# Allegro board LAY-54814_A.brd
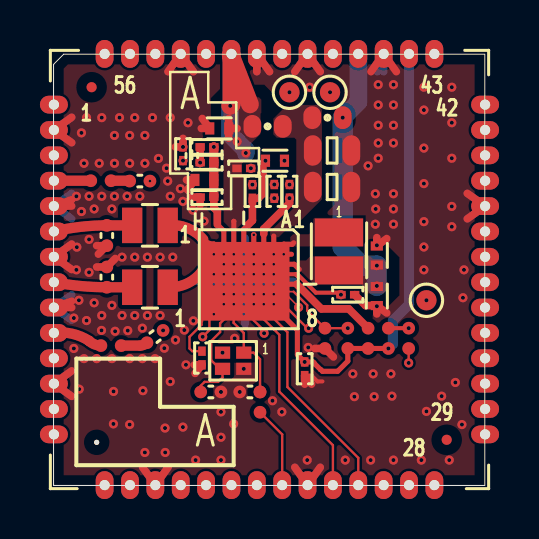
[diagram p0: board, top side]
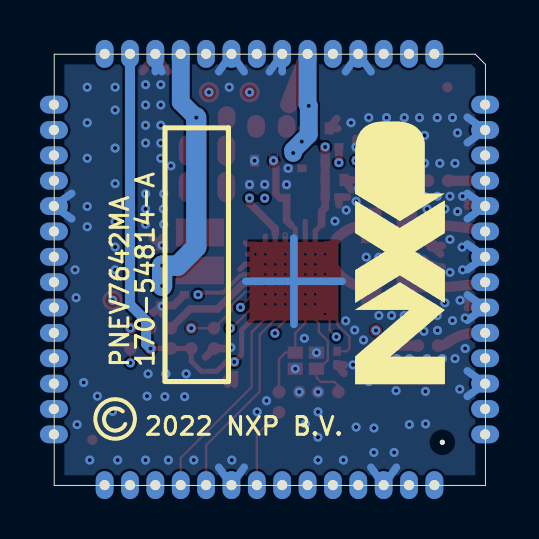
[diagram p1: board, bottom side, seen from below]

Outline 21.59 x 21.59 mm; copper layers: TOP, L2_GND_1, L3_INT_1, L4_INT_2, L5_GND_2, BOTTOM. Coordinates in mm from the lower left corner of the outline.
Outline path: 0,21.08 0,0 21.59,0 21.59,21.59 0.51,21.59 0,21.08

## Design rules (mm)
constraint set DEFAULT: min track width 0.117
net group USB: nets ATX_C ATX_D
net group PWR: nets VBAT VDDIO VDDPA

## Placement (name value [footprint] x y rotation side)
C1  18PF  [CC0402_25]  9.83 4.68 180 top
C2  18PF  [CC0402_25]  7.87 4.68 0 top
C5  0.1uF  [CC0201]  7.43 6.38 270 top
C7  1000pF  [CC0402_25]  5.08 7.45 217.3 top
C8  0.1uF  [CC0201]  12.57 5.84 270 top
C9  0.22uF  [CC0201]  14.73 9.55 0 top
C10  4.7uF  [CC0402_TOL0P15]  16.19 9.48 270 top
C11  0.22uF  [CC0201]  11.81 14.73 90 top
C12  560pF  [CC0402_25]  2.67 10.43 90 top
C13  4.7uF  [CC0402_TOL0P15]  16.19 11.51 90 top
C14  560pF  [CC0402_25]  2.67 12.51 270 top
C15  100pF  [CC0201]  7.68 14.43 180 top
C16  0.1uF  [CC0201]  11.05 14.72 90 top
C17  1uf  [CC0201]  9.96 14.72 90 top
C19  22uF  [CC0805_OV]  13.94 14.94 0 top
C20  4.7uF  [CC0402_TOL0P15]  7.55 15.3 180 top
C21  1000pF  [CC0402_25]  4.32 15.24 180 top
C22  100pF  [CC0201]  9.52 15.88 0 top
C23  100pF  [CC0201]  7.68 16.16 0 top
C24  4.7uF  [CC0402_TOL0P15]  11.09 16.26 0 top
C26  0.22uF  [CC0201]  6.48 16.61 90 top
C27  22uF  [CC0805_OV]  13.94 16.77 0 top
C28  0.22uF  [CC0201]  7.68 16.95 0 top
C29  4.7uF  [CC0402_TOL0P15]  8.29 17.88 180 top
L1  160nH  [IND0805HQ]  4.83 9.92 180 top
L2  1.0uH  [IND_1008_SMD]  14.29 11.72 270 top
L3  160nH  [IND0805HQ]  4.83 13.02 180 top
NOREF  -  []  10.18 0.02 0 top
NOREF#2  -  [unnamed#2]  2.16 2.16 270 top
NOREF#3  -  []  -27.72 -40.64 0 top
NOREF#4  -  []  8.14 6.89 0 top
NOREF#5  -  []  14.71 9.41 90 top
NOREF#6  -  []  7.07 15.3 0 top
NOREF#7  -  []  -53.92 -161.42 0 top
NOREF#8  -  [unnamed#2]  1.9 19.94 180 top
NOREF#9  -  []  7.47 8.02 0 top
NOREF#10  -  []  6.97 14.97 90 top
NOREF#11  -  []  14.71 10.06 0 top
NOREF#12  -  []  21.61 5.1 90 top
NOREF#13  -  []  -267.27 261.62 0 top
NOREF#14  -  []  7.37 12.19 0 top
NOREF#15  -  []  7.82 17.88 0 top
NOREF#16  -  []  7.72 18.2 0 top
NOREF#17  -  []  15.36 10.29 90 top
NOREF#18  -  []  9.84 5.59 90 top
NOREF#19  -  []  2.16 2.16 0 top
NOREF#20  -  []  16.19 9.01 90 top
NOREF#21  -  []  10.61 16.26 0 top
NOREF#22  -  []  7.37 8.25 90 top
NOREF#23  -  []  9.52 5.84 90 top
NOREF#24  -  []  7.72 17.55 90 top
NOREF#25  -  []  0.02 0.02 0 top
NOREF#26  -  []  21.61 2.56 90 top
NOREF#27  -  []  15.36 10.94 0 top
NOREF#28  -  []  8.46 6.65 0 top
NOREF#29  -  []  16.19 11.04 90 top
NOREF#30  -  [unnamed#2]  19.68 2.29 180 top
NOREF#31  -  []  -294.83 -257.94 0 top
NOREF#32  -  []  21.61 0.02 90 top
NOREF#33  -  []  7.47 8.02 90 top
NOREF#34  -  []  11.66 15.93 90 top
NOREF#35  -  []  6.97 15.62 0 top
NOREF#36  -  []  10.51 15.93 0 top
NOREF#37  -  []  18.54 3.3 180 bottom
NOREF#38  -  []  2.03 5.08 90 bottom
NOREF#39  -  []  16.55 17.39 270 bottom
P1  PN76xx-M  [MODULE56_1P52_25X25MM]  10.81 10.81 0 top
R1  0  [RC0402_25]  10.34 4.17 90 top
R2  0  [RC0402_25]  2.88 7 180 top
R3  0  [RC0402_25]  2.37 15.26 180 top
R4  0  [RC0603_OV]  10.72 17.98 180 top
R5  0  [RC0402_25]  15.75 7.37 270 top
R6  0  [RC0402_25]  13.59 7.37 90 top
R7  0  [RC0402_25]  14.73 7.37 90 top
R8  0  [RC0603_OV]  13.72 18.41 180 top
R9  10.0K  [RC0402_25]  16.76 7.37 90 top
R10  0  [RC0402_25]  17.78 7.37 270 top
TP1  -  [TPAD_040]  13.84 19.68 180 top
TP2  -  [TPAD_040]  11.81 19.68 180 top
TP3  -  [TPAD_040]  18.67 9.27 180 top
U1  PN7642EV/C100  [VFBGA64_0P5_4P6X4P6]  9.77 10.32 270 top
Y1  27.12MHz  [XTAL4_1P6X1P2]  8.99 6.24 180 top

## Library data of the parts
C1 C2 C7 C10 C12-C14 C19-C21 C24 C27 C29 = CAP_NP
C5 C8 C16 = CAP_NP: Tolerance: TOLERANCE; User Part Number: 150-80059
C9 C11 C26 C28 = CAP_NP: Tolerance: TOLERANCE; User Part Number: 150-79474
C15 C22 C23 = CAP_NP: Tolerance: TOLERANCE; User Part Number: 150-75742
C17 = CAP_NP: Tolerance: TOLERANCE; User Part Number: 150-79855
L1 L3 = INDUCTOR: tolerance: 5%
L2 = INDUCTOR: tolerance: 20%
P1 = TP_RECT_56P_EP
R1-R8 R10 = RES
R9 = RES: tolerance: 5%
TP1-TP3 = TESTLOOP
U1 = PN7642EV_VBGA64
Y1 = XTAL_13

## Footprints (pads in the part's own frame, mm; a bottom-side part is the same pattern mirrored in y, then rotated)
CC0201
  rect 0.47x0.381 smd: 1(-0.343,0) 2(0.343,0)
CC0402_25
  round 0.635 smd: 1(-0.508,0) 2(0.508,0)
CC0402_TOL0P15
  rect 0.457x0.61 smd: 1(-0.475,0) 2(0.475,0)
CC0805_OV
  oval 0.889x1.524 smd: 1(-0.965,0) 2(0.965,0)
IND0805HQ
  rect 1.016x1.778 smd: 1(-0.889,0) 2(0.889,0)
IND_1008_SMD
  rect 1.397x2.413 smd: 1(-0.95,0) 2(0.95,0)
MODULE56_1P52_25X25MM
  oval 1.397x0.889 hole 0.508: 1(-10.795,8.255) 2(-10.795,6.985) 3(-10.795,5.715) 4(-10.795,4.445) 5(-10.795,3.175) 6(-10.795,1.905) 7(-10.795,0.635) 8(-10.795,-0.635) 9(-10.795,-1.905) 10(-10.795,-3.175) 11(-10.795,-4.445) 12(-10.795,-5.715) 13(-10.795,-6.985) 14(-10.795,-8.255) 29(10.795,-8.255) 30(10.795,-6.985) 31(10.795,-5.715) 32(10.795,-4.445) 33(10.795,-3.175) 34(10.795,-1.905) 35(10.795,-0.635) 36(10.795,0.635) 37(10.795,1.905) 38(10.795,3.175) 39(10.795,4.445) 40(10.795,5.715) 41(10.795,6.985) 42(10.795,8.255)
  oval 0.889x1.397 hole 0.508: 15(-8.255,-10.795) 16(-6.985,-10.795) 17(-5.715,-10.795) 18(-4.445,-10.795) 19(-3.175,-10.795) 20(-1.905,-10.795) 21(-0.635,-10.795) 22(0.635,-10.795) 23(1.905,-10.795) 24(3.175,-10.795) 25(4.445,-10.795) 26(5.715,-10.795) 27(6.985,-10.795) 28(8.255,-10.795) 43(8.255,10.795) 44(6.985,10.795) 45(5.715,10.795) 46(4.445,10.795) 47(3.175,10.795) 48(1.905,10.795) 49(0.635,10.795) 50(-0.635,10.795) 51(-1.905,10.795) 52(-3.175,10.795) 53(-4.445,10.795) 54(-5.715,10.795) 55(-6.985,10.795) 56(-8.255,10.795)
  rect 4.445x3.937 smd: 57(-1.224,-0.589)
RC0402_25
  round 0.635 smd: 1(-0.508,0) 2(0.508,0)
RC0603_OV
  oval 0.889x1.143 smd: 1(-0.762,0) 2(0.762,0)
TPAD_040
  round 1.016 smd: 1(0,0)
unnamed#2
  round 0.254 hole 0.635 unplated: (0,0)
VFBGA64_0P5_4P6X4P6
  round 0.279 smd: A1(-1.75,1.75) A2(-1.25,1.75) A3(-0.75,1.75) A4(-0.25,1.75) A5(0.25,1.75) A6(0.75,1.75) A7(1.25,1.75) A8(1.75,1.75) B1(-1.75,1.25) B2(-1.25,1.25) B3(-0.75,1.25) B4(-0.25,1.25) B5(0.25,1.25) B6(0.75,1.25) B7(1.25,1.25) B8(1.75,1.25) C1(-1.75,0.75) C2(-1.25,0.75) C3(-0.75,0.75) C4(-0.25,0.75) C5(0.25,0.75) C6(0.75,0.75) C7(1.25,0.75) C8(1.75,0.75) D1(-1.75,0.25) D2(-1.25,0.25) D3(-0.75,0.25) D4(-0.25,0.25) D5(0.25,0.25) D6(0.75,0.25) D7(1.25,0.25) D8(1.75,0.25) E1(-1.75,-0.25) E2(-1.25,-0.25) E3(-0.75,-0.25) E4(-0.25,-0.25) E5(0.25,-0.25) E6(0.75,-0.25) E7(1.25,-0.25) E8(1.75,-0.25) F1(-1.75,-0.75) F2(-1.25,-0.75) F3(-0.75,-0.75) F4(-0.25,-0.75) F5(0.25,-0.75) F6(0.75,-0.75) F7(1.25,-0.75) F8(1.75,-0.75) G1(-1.75,-1.25) G2(-1.25,-1.25) G3(-0.75,-1.25) G4(-0.25,-1.25) G5(0.25,-1.25) G6(0.75,-1.25) G7(1.25,-1.25) G8(1.75,-1.25) H1(-1.75,-1.75) H2(-1.25,-1.75) H3(-0.75,-1.75) H4(-0.25,-1.75) H5(0.25,-1.75) H6(0.75,-1.75) H7(1.25,-1.75) H8(1.75,-1.75)
XTAL4_1P6X1P2
  rect 0.762x0.61 smd: 1(-0.531,-0.405) 2(0.531,-0.405) 3(0.531,0.405) 4(-0.531,0.405)

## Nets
GND: C1.2 C2.2 C5.2 C8.2 C9.2 C10.2 C11.2 C12.2 C13.2 C14.2 C15.2 C16.2 C17.2 C19.2 C20.2 C22.2 C24.2 C26.2 C27.2 C29.2 P1.2 P1.5 P1.7 P1.9 P1.12 P1.17 P1.23 P1.38 P1.45 P1.48 P1.50 P1.53 P1.57(EPAD) R6.1 U1.A2 U1.B2 U1.C3 U1.D3 U1.E3 U1.F3 U1.F4 U1.G3 U1.H2 Y1.2 Y1.4
PVDDOUT: R5.1 U1.A5
VBAT: C17.1 C24.1 P1.49 U1.E1
VBATPWR: C10.1 C13.1 L2.2 P1.46 R8.1 U1.A3
VDDBOOST: C19.1 C27.1 R4.1 R8.2 U1.B1
VDDC: C11.1 TP1.1(PIN1) U1.C1
VDDIO: C8.1 P1.44 R5.2 R7.1 R9.1 U1.A8
VDDNV: C9.1 TP3.1(PIN1) U1.A4
VDDPA: C15.1 C20.1 C23.2 C28.2 P1.52 U1.G1
AD1: P1.1 U1.E2
ATX_A: P1.34 U1.E6
ATX_B: P1.35 U1.E5
ATX_C: P1.36 U1.D6
ATX_D: P1.37 U1.D5
AUX1: P1.18 U1.G7
AUX2: P1.19 U1.F7
BOOST_LX: L2.1 U1.A1
C_RXN: C21.2 R3.1
C_RXP: C7.2 R2.1
CLK_IN: P1.22 R1.1
CT_CLK: P1.56 U1.E4
CT_INT: P1.54 U1.C4
CT_IO: P1.55 U1.D4
DWL_REQ: P1.27 U1.A7
GPIO0: P1.28 U1.E8
GPIO1: P1.31 U1.D8
GPIO2: P1.29 U1.E7
GPIO3: P1.30 U1.D7
GPIO4: P1.32 U1.C5
GPIO5: P1.33 U1.B5
HOSTIF_SEL0: P1.20 U1.C7
HOSTIF_SEL1: P1.21 U1.C6
I2CM_SCL: P1.40 U1.B6
I2CM_SDA: P1.39 U1.A6
IRQ: P1.26 U1.B7
MOD_RXN: P1.4 R3.2
MOD_RXP: P1.10 R2.2
MOD_TX1: C14.1 L3.2 P1.6
MOD_TX2: C12.1 L1.2 P1.8
MOD_VEN: P1.43 R10.2
PRD1: P1.41 U1.B4
PRD2: P1.42 U1.G4
RXN: C21.1 U1.H4
RXP: C7.1 U1.H5
SPIM_MISO: P1.16 U1.F6
SPIM_MOSI: P1.13 U1.F5
SPIM_NSS: P1.15 U1.G6
SPIM_SCLK: P1.14 U1.G5
SWDCLK: P1.24 U1.C8
SWDIO: P1.25 U1.B8
TCVCM: C26.1 U1.G2
TEST: R6.2 R7.2 U1.C2
TX1: L3.1 U1.H1
TX2: L1.1 U1.H3
TXVCASC: C23.1 C28.1 U1.F2
USB_VBUS: P1.47 U1.D1
VEN: R9.2 R10.1 U1.B3
VMID: C5.1 U1.H6
VREF: C16.1 TP2.1(PIN1) U1.D2
VTUNE1: P1.11 U1.H7
VTUNE2: P1.3 U1.H8
VUP: C22.1 C29.1 P1.51 R4.2 U1.F1
XTAL1: C1.1 R1.2 U1.F8 Y1.1
XTAL2: C2.1 U1.G8(XTAL2) Y1.3

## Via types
v1: diameter 0.457, hole 0.203, TOP to BOTTOM, 141 vias
v2: diameter 0.279, hole 0.13, TOP to L2_GND_1, 43 vias
v3: diameter 0.254, hole 0.13, L2_GND_1 to L3_INT_1, 34 vias
v4: diameter 0.279, hole 0.13, L3_INT_1 to L4_INT_2, 17 vias
v5: diameter 0.457, hole 0.206, TOP to BOTTOM, 31 vias

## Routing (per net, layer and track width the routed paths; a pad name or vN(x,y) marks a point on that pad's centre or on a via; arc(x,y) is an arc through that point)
GND: length 152.7
  TOP w0.203: C8.2 12.92,5.5 13.21,5.21 13.46,5.21
  TOP w0.254: 11.91,11.57 v2(11.52,11.57) v2(11.02,11.57)
  TOP w0.279: v2(8.02,11.57) 7.51,11.57
  TOP w0.381: 15.89,20.72 P1.45 17.16,20.72 ; 20.72,13.35 P1.38 20.72,14.62 ; 13.35,20.72 P1.48 12.08,20.72 ; 0.91,4.46 P1.12 0.91,5.73 ; 7.09,5.61 C5.2 7.05,6.04 ; 2.16,10.94 C12.2 3.09,11.36 ; 5.73,20.72 P1.53 7,20.72 ; 0.91,17.16 P1.2 0.91,18.43 ; 5.73,0.91 P1.17 4.46,0.91 ; 6.66,15.3 C20.2 6.7,14.8 ; 16.19,12.41 C13.2 16.68,12.36 ; 7.4,17.88 C29.2 7.45,18.37 ; 2.16,12.01 C14.2 2.24,11.58 ; 0.91,8.91 P1.9 0.91,9.22 ; 14.01,6.43 R6.1 13.08,6.86 ; 0.91,10.81 P1.7 0.91,12.08 ; C10.2 15.62,9.01 C9.2 ; C10.2 16.68,8.63 ; C10.2 16.19,8.59 ; 12.08,0.91 P1.23 13.35,0.91 ; 0.91,14.3 P1.5 0.91,13.99 ; 6.91,14.43 C15.2 7.34,14.05 ; 12.92,5.07 C8.2 12.57,5.07 ; 6.1,16.95 v5(6.48,16.95) 6.48,17.38 ; 10.81,20.72 P1.50 10.18,20.72
  L2_GND_1 w0.381: 0.91,14.62 P1.5 0.91,13.35 ; 10.81,20.72 P1.50 9.54,20.72 ; 20.72,14.62 P1.38 20.72,13.35 ; 7,20.72 P1.53 5.73,20.72 ; 15.89,20.72 P1.45 17.16,20.72 ; 0.91,5.73 P1.12 0.91,4.46 ; 4.46,0.91 P1.17 5.73,0.91 ; 12.08,0.91 P1.23 13.35,0.91 ; 0.91,9.54 P1.9 0.91,8.27 ; 0.91,10.81 P1.7 0.91,12.08 ; 13.35,20.72 P1.48 12.08,20.72 ; 0.91,18.43 P1.2 0.91,17.16
  L4_INT_2 w0.381: 20.72,13.35 P1.38 20.72,14.62 ; 12.08,0.91 P1.23 13.35,0.91 ; 0.91,17.16 P1.2 0.91,18.43 ; 0.91,5.73 P1.12 0.91,4.46 ; 12.72,20.72 P1.48 12.4,20.72 ; 5.73,20.72 P1.53 6.37,20.72 ; 0.91,9.54 P1.9 0.91,8.27 ; 10.18,20.72 P1.50 9.86,20.72 ; 0.91,10.81 P1.7 0.91,12.08 ; 5.73,0.91 P1.17 4.46,0.91 ; 0.91,13.35 P1.5 0.91,14.62 ; 15.89,20.72 P1.45 17.16,20.72
  L5_GND_2 w0.381: 17.16,20.72 P1.45 15.89,20.72 ; 0.91,12.08 P1.7 0.91,10.81 ; 0.91,14.62 P1.5 0.91,13.35 ; 10.81,20.72 P1.50 9.54,20.72 ; 12.08,20.72 P1.48 13.35,20.72 ; 5.73,0.91 P1.17 4.46,0.91 ; 13.35,0.91 P1.23 12.08,0.91 ; 0.91,8.27 P1.9 0.91,9.54 ; 0.91,5.73 P1.12 0.91,4.46 ; 7,20.72 P1.53 5.73,20.72 ; 20.72,13.35 P1.38 20.72,14.62 ; 0.91,17.16 P1.2 0.91,18.43
  BOTTOM w0.381: 12.08,0.91 P1.23 13.35,0.91 ; 0.91,9.54 P1.9 0.91,8.27 ; 10.18,20.72 P1.50 10.81,20.72 ; 7,20.72 P1.53 5.73,20.72 ; 7.17,10.22 P1.57 ; P1.57 9.59,12.38 ; P1.57 9.59,8.06 ; P1.57 12,10.22 ; 0.91,12.08 P1.7 0.91,10.81 ; 13.35,20.72 P1.48 12.08,20.72 ; 4.46,0.91 P1.17 5.73,0.91 ; 16.21,20.72 P1.45 16.53,20.72 ; 0.91,4.46 P1.12 0.91,5.73 ; 20.72,14.62 P1.38 20.72,13.35 ; 0.91,14.62 P1.5 0.91,13.35 ; 0.91,18.43 P1.2 0.91,17.16
  vias: v1(1.02,8.38) v1(1.02,6.86) v1(1.14,14.48) v1(1.17,11.93) v1(1.14,10.79) v1(1.27,9.27) v1(1.28,4.82) v1(1.4,17.65) v1(1.4,13.72) v1(1.52,16.13) v1(1.52,6.35) v1(1.65,18.41) v1(1.65,8.25) v1(1.78,14.48) v1(1.78,12.32) v1(1.78,10.67) v1(2.03,13.84) v1(2.03,9.14) v1(2.16,6.35) v1(2.29,16.13) v1(2.4,7.76) v1(2.41,18.41) v1(2.41,14.48) v1(2.41,8.51) v1(2.92,13.84) v1(2.92,9.02) v1(2.92,6.35) v1(3,4.71) v1(3,3.08) v1(3.05,17.53) v1(3.05,16.13) v1(3.05,14.48) v1(3.08,7.72) v1(3.3,18.41) v1(3.43,11.43) v1(3.43,8.51) v1(3.68,14.48) v1(3.72,7.75) v1(3.81,17.53) v1(3.81,16.13) v1(3.81,6.35) v1(3.81,3.05) v1(4.06,18.41) v1(4.06,11.43) v1(4.06,8.51) v1(4.32,14.48) v1(4.45,7.87) v1(4.45,6.35) v1(4.47,4.74) v1(4.57,17.53) v1(4.57,16.13) v1(4.57,1.65) v1(4.7,11.43) v1(4.7,8.51) v1(4.95,18.41) v1(5.08,6.35) v1(5.25,16.37) v1(5.33,11.43) v1(5.33,8.51) v1(5.55,6.87) v1(5.58,2.87) v1(5.59,1.65) v1(5.66,15.88) v1(5.71,15.24) v1(5.84,18.41) v1(5.84,14.48) v1(5.84,5.2) v1(5.97,11.43) v1(6.11,7.28) v1(6.35,14.86) v1(6.48,14.22) v1(6.48,2.92) v1(6.55,7.78) v1(6.63,6.04) v1(6.73,18.16) v1(6.97,13.79) v1(7,8.24) v1(7.11,1.27) v1(7.53,13.23) v1(8.38,3.68) v1(8.38,2.41) v1(8.38,1.27) v1(9.07,7.37) v1(9.02,3.08) v1(10.96,4.24) v1(11.43,3.68) v1(12.7,1.27) v1(12.75,6.91) v1(12.83,19.94) v1(14.61,1.27) v1(14.99,5.59) v1(15.06,4.45) v1(15.75,16) v1(15.88,1.27) v1(16,5.59) v1(16.05,4.45) v1(16.11,14.6) v1(16.13,13.84) v1(16.11,13.08) v1(16.26,20.07) v1(16.26,19.05) v1(16.26,18.03) v1(16.26,17.14) v1(16.26,16.38) v1(16.89,5.59) v1(16.94,4.47) v1(17.02,20.07) v1(17.02,19.05) v1(17.02,18.03) v1(17.02,17.14) v1(17.02,14.61) v1(17.02,13.84) v1(17.02,13.08) v1(17.02,1.27) v1(18.41,1.27) v1(18.54,19.94) v1(18.54,18.8) v1(18.54,16.89) v1(18.54,15.11) v1(18.54,13.21) v1(18.54,11.94) v1(18.54,10.79) v1(18.67,3.71) v1(19.43,4.47) v1(19.81,1.27) v1(19.94,19.94) v1(19.94,18.16) v1(19.94,16.38) v1(19.94,13.97) v1(19.94,12.95) v1(20.12,5.16) v1(20.5,9.4) v1(20.45,3.05) v1(20.55,10.79) v2(8.53,11.07) v2(9.02,11.07) v2(9.02,10.57) v2(9.52,11.07) v2(10.02,11.07) v2(10.52,11.07) v5(8.38,4.68) v5(8.46,6.65) v5(9.32,4.68) v5(9.52,5.84) v5(9.88,15.88) v5(9.96,15.06) v5(11.05,15.07) v5(11.56,16.26) v5(11.81,15.06) v5(16.19,12.02) v5(16.19,8.97)
PVDDOUT: length 5.1
  TOP w0.117: 12.09,10.07 12.18,10.07
  TOP w0.254: U1.A5 12.09,10.07
  TOP w0.381: 12.18,10.07 13.41,8.84 14.78,8.84 R5.1
VBAT: length 10.5
  TOP w0.254: U1.E1 9.52,12.83 9.74,13.05
  TOP w0.356: C17.1 10.27,14.38 10.49,14.6 10.49,16.14 v5(10.61,16.26)
  TOP w0.381: C17.1 9.96,13.27 9.74,13.05
  L4_INT_2 w0.508: P1.49 11.45,20.72 10.79,20.07 10.79,16.44 v5(10.61,16.26)
VBATPWR: length 27.1
  TOP w0.254: 12.3,10.82 12.05,11.07 U1.A3
  TOP w0.381: C13.1 16.2,11.05
  L3_INT_1 w0.889: v5(14.48,18.41) 15.26,19.19 P1.46
  L3_INT_1 w1.016: v5(14.48,18.41) 14.48,11.94 15.41,11.01 v5(16.19,11.01) v5(16.19,9.99)
  BOTTOM w0.889: v5(14.48,18.41) 15.26,19.19 P1.46
  BOTTOM w1.016: v5(16.19,9.99) v5(16.19,11.01) 15.41,11.01 14.48,11.94 v5(14.48,18.41)
VDDBOOST: length 0.4
  TOP w0.254: U1.B1 11.02,12.49
VDDC: length 9
  TOP w0.254: U1.C1 10.52,12.6
  TOP w0.381: 10.52,12.6 10.52,12.84 11.81,14.13 v5(11.81,14.38)
  L4_INT_2 w0.203: v5(13.84,19.68) 12.85,18.69 12.85,15.42 v5(11.81,14.38)
VDDIO: length 23.2
  TOP w0.254: U1.A8 11.52,8.47 12.21,7.78 12.21,6.55 v5(12.57,6.18) 12.99,6.18 13.04,6.13 13.04,6.12 13.36,5.8 13.37,5.8 13.46,5.71 14.22,5.71 14.73,6.22 R7.1 R5.2 v5(16.76,6.86)
  BOTTOM w0.508: P1.44 17.8,9.06 16.99,8.25 16.99,7.09 v5(16.76,6.86)
VDDNV: length 8.4
  TOP w0.203: U1.A4 12.12,10.57 12.18,10.51 12.27,10.51 13.13,9.65 14.29,9.65 v5(14.39,9.55)
  L3_INT_1 w0.203: v5(18.67,9.27) 17.78,8.38 15.56,8.38 v5(14.39,9.55)
VDDPA: length 9.9
  TOP w0.254: 8.2,13.07 8.53,12.74 U1.G1
  TOP w0.381: C15.1 8.02,13.91 8.2,13.73 8.2,13.07
  TOP w0.457: C15.1 C20.1 C23.2 v5(8.02,16.95)
  L4_INT_2 w0.508: v5(8.02,16.95) 7.64,17.34 P1.52
AD1: length 15.5
  L3_INT_1 w0.076: 9.52,13.11 v3(9.52,11.57)
  L3_INT_1 w0.102: 9.52,13.11 9.52,15.27 8.51,16.28 8.51,17.45 6.89,19.07 P1.1
ATX_A: length 21.4
  L4_INT_2 w0.076: 10.81,8.29 v4(9.52,9.57)
  L4_INT_2 w0.102: P1.34 20.78,8.91 20.68,8.81 20.68,4.93 18.75,3 12.85,3 11.13,4.72 11.13,7.97 10.81,8.29
ATX_B: length 19.3
  L3_INT_1 w0.102: v4(18.72,6.55) 19.58,7.42 19.58,9.27 20.49,10.18 P1.35
  L4_INT_2 w0.076: v4(9.52,10.07) 9.87,10.41 10.16,10.41 12.25,8.33 12.96,8.33 13,8.29
  L4_INT_2 w0.102: v4(18.72,6.55) 18.72,5.92 17.68,4.88 14.43,4.88 13.36,5.94 13.36,7.28 13.23,7.41 13.23,8.06 13,8.29
ATX_C: length 22.8
  L4_INT_2 w0.107: P1.36 20.73,11.45 20.62,11.55 20.62,11.82 20.51,11.93 20.36,11.93 19.99,11.56 19.99,5.84 17.83,3.68 13.31,3.68 11.73,5.26 11.73,8 10.16,9.57 v4(10.02,9.57)
ATX_D: length 22.8
  L4_INT_2 w0.107: P1.37 20.73,12.72 20.62,12.61 20.62,12.34 20.51,12.24 20.24,12.24 19.68,11.69 19.68,5.97 17.7,3.99 13.44,3.99 12.04,5.39 12.04,8.13 10.24,9.93 10.16,9.93 v4(10.02,10.07)
AUX1: length 10
  L3_INT_1 w0.076: 8.53,8.29 v3(8.53,9.07)
  L3_INT_1 w0.102: P1.18 6.37,1.67 6.98,2.29 6.98,5.36 7.77,6.15 7.77,6.71 8.28,7.21 8.28,7.62 8.53,7.86 8.53,8.29
AUX2: length 9.9
  L3_INT_1 w0.076: 9.02,8.29 v3(9.02,9.07)
  L3_INT_1 w0.102: 9.02,8.29 9.02,7.98 8.59,7.54 8.59,7.19 8.89,6.88 8.89,6.25 7.64,5 P1.19
BOOST_LX: length 0.5
  TOP w0.254: 12.02,12.15 11.95,12.07 U1.A1
C_RXN: length 0.9
  TOP w0.516: 3.81,15.24 3.79,15.26 R3.1
C_RXP: length 1.3
  TOP w0.516: R2.1 4.33,7 arc(4.52,7.04) C7.2
CLK_IN: length 4.1
  TOP w0.117: R1.1 11.45,2.56 P1.22
CT_CLK: length 20.9
  L3_INT_1 w0.076: 12.14,12.85 11.23,11.94 10.89,11.94 v3(9.52,10.57) ; 12.14,12.85 12.14,13.11 ; 12.14,12.85 12.4,13.11 12.4,13.11
  L3_INT_1 w0.102: 12.14,13.82 12.14,13.11 ; P1.56 2.56,20.3 3.14,19.72 9,19.72 12.4,16.33 12.4,13.11
CT_INT: length 18.1
  L3_INT_1 w0.076: 13.16,13.11 13.16,13.03 11.56,11.43 11,11.43 10.52,10.96 v3(10.52,10.57)
  L3_INT_1 w0.102: P1.54 5.1,20.68 5.33,20.45 9.27,20.45 13.16,16.56 13.16,13.11
CT_IO: length 19.1
  L3_INT_1 w0.076: v3(10.02,10.57) 10.02,10.74 10.97,11.68 11.37,11.68 12.8,13.11
  L3_INT_1 w0.102: 12.8,13.11 12.8,16.41 9.14,20.07 4.06,20.07 3.83,20.3 P1.55
DWL_REQ: length 12
  TOP w0.076: 11.62,8.95 11.52,9.05 U1.A7
  TOP w0.117: 11.62,8.95 12.7,7.87 v1(12.77,7.87)
  L3_INT_1 w0.102: v1(12.77,7.87) 13.73,6.91 13.73,5.12 16.31,2.54 16.89,2.54 17.8,1.63 P1.27
GPIO0: length 17.4
  L3_INT_1 w0.076: 9.52,8.29 v3(9.52,8.57)
  L3_INT_1 w0.102: v4(8.84,5.46) 8.84,5.73 9.52,6.42 9.52,8.29
  L4_INT_2 w0.102: v4(8.84,5.46) 8.84,4.17 11.33,1.68 18.64,1.68 19.07,1.25 P1.28
GPIO1: length 17.4
  TOP w0.076: 10.02,8.29 U1.D8
  TOP w0.117: v5(10.54,7.62) 10.54,7.75 10.02,8.26 10.02,8.29
  L4_INT_2 w0.102: P1.31 20.83,4.32 20.5,4.32 18.87,2.69 11.79,2.69 10.54,3.94 v5(10.54,7.62)
GPIO2: length 18.3
  L3_INT_1 w0.076: v3(9.52,9.07) 9.8,8.79 9.8,8.29
  L3_INT_1 w0.102: 9.8,8.29 9.8,6.32 9.98,6.15 9.98,5.61 9.86,5.49 v4(9.86,5.23)
  L4_INT_2 w0.102: P1.29 20.08,2.56 19.51,1.98 11.63,1.98 9.86,3.76 v4(9.86,5.23)
GPIO3: length 18
  L3_INT_1 w0.076: 10.03,8.29 10.03,8.41 10.02,8.42 v3(10.02,9.07)
  L3_INT_1 w0.102: 10.03,8.29 10.03,6.68 10.22,6.49 v4(10.22,6.48)
  L4_INT_2 w0.102: P1.30 20.59,3.83 19.08,2.31 11.73,2.31 10.22,3.82 v4(10.22,6.48)
GPIO4: length 15.2
  L3_INT_1 w0.076: v3(10.52,10.07) 10.77,9.83 11.96,9.83 12.67,9.12 12.67,8.81 13.2,8.29
  L3_INT_1 w0.102: P1.32 20.59,6.37 19.1,4.88 14.55,4.88 13.96,5.47 13.96,7.53 13.2,8.29
GPIO5: length 15
  L3_INT_1 w0.076: v3(11.02,10.07) 12.15,10.07 12.95,9.27 12.95,8.97 13.21,8.71
  L3_INT_1 w0.102: 13.21,8.71 14.25,7.67 14.25,5.66 14.76,5.16 18.19,5.16 20.67,7.64 P1.33
HOSTIF_SEL0: length 10.2
  L3_INT_1 w0.076: v3(10.52,9.07) 10.52,8.35 10.58,8.29
  L3_INT_1 w0.102: P1.20 8.91,1.92 9.86,2.87 9.86,4.78 10.44,5.36 10.44,6.2 11.07,6.83 11.07,7.8 10.58,8.29
HOSTIF_SEL1: length 10.5
  L3_INT_1 w0.076: v3(10.52,9.57) 10.77,9.33 10.77,8.74 11.22,8.29
  L3_INT_1 w0.102: 11.22,8.29 11.51,8 11.51,6.93 10.69,6.12 10.69,4.88 10.18,4.36 P1.21
I2CM_SCL: length 20.9
  L3_INT_1 w0.076: v4(11.51,9.57) v3(11.02,9.57)
  L4_INT_2 w0.076: 13.21,8.82 13.05,8.82 12.3,9.57 v4(11.51,9.57)
  L4_INT_2 w0.102: 13.21,8.82 13.33,8.82 13.84,8.31 13.84,8.03 15.65,6.22 17.14,6.22 17.65,6.73 17.91,6.73 18.54,7.37 18.54,8.48 18.08,8.94 18.08,13.89 20.72,16.53 P1.40
I2CM_SDA: length 21.5
  TOP w0.076: U1.A6 11.64,9.57 12.27,8.94 v1(12.27,8.92)
  L4_INT_2 w0.076: 13.21,8.51 13.13,8.59 12.72,8.59 12.39,8.92 12.28,8.92 v1(12.27,8.92)
  L4_INT_2 w0.102: 13.21,8.51 13.53,8.19 13.53,7.9 13.69,7.75 13.69,6.12 14.63,5.18 17.5,5.18 18.34,6.02 18.34,6.71 18.85,7.21 18.85,8.74 19.18,9.07 19.18,14.1 20.34,15.26 P1.39
IRQ: length 11.3
  L3_INT_1 w0.076: 11.81,8.29 v3(11.02,9.07)
  L3_INT_1 w0.102: 11.81,8.29 11.89,8.21 11.89,6.05 16.53,1.41 P1.26
MOD_RXN: length 1.8
  TOP w0.516: R3.2 P1.4
MOD_RXP: length 2.5
  TOP w0.516: P1.10 arc(0.93,7.59) 1.78,7.24 1.78,7.24 arc(2.05,7.06) R2.2
MOD_TX1: length 3.9
  TOP w0.516: L3.2 C14.1 arc(1.33,12.95) P1.6
MOD_TX2: length 3.9
  TOP w0.516: L1.2 C12.1 arc(1.34,9.99) P1.8
MOD_VEN: length 16.8
  TOP w0.117: R10.2 v1(17.78,6.13)
  L3_INT_1 w0.102: v1(17.78,6.13) 19.18,7.53 19.18,19.56 19.07,19.67 P1.43
PRD1: length 21.5
  L4_INT_2 w0.076: 13.21,10.06 12.69,10.57 v4(11.02,10.57)
  L4_INT_2 w0.102: P1.41 20.34,17.8 17.68,15.14 17.68,8.74 18.24,8.18 18.24,7.49 18.14,7.39 15.88,7.39 13.21,10.06
PRD2: length 16.8
  L3_INT_1 w0.076: v3(8.53,10.57) 8.53,10.89 v4(8.71,11.07)
  L4_INT_2 w0.076: v4(8.71,11.07) 10.24,11.07 10.69,11.53 11.91,11.53 13.21,12.83
  L4_INT_2 w0.102: 13.21,12.83 15.75,15.37 16.18,15.37 19.88,19.07 P1.42
RXN: length 5.8
  L3_INT_1 w0.279: v3(8.02,10.57) arc(7.74,10.63) 7.49,10.79
  L3_INT_1 w0.533: v3(4.83,15.24) 4.92,14.91 arc(5.78,12.9) 7.12,11.16 7.49,10.79
RXP: length 3.5
  L3_INT_1 w0.279: 7.11,9.23 7.91,10.03 arc(7.96,10.06) v3(8.02,10.07)
  L3_INT_1 w0.516: 7.11,9.23 5.76,7.87 arc(5.63,7.79) v5(5.48,7.76)
SPIM_MISO: length 12.5
  L4_INT_2 w0.076: v4(9.02,9.57) 9.55,9.05 9.55,8.29
  L4_INT_2 w0.102: P1.16 3.83,1.8 5.31,3.28 5.92,3.28 9.55,6.91 9.55,8.29
SPIM_MOSI: length 12.1
  L4_INT_2 w0.076: 7.67,8.29 8.25,8.88 8.25,9.7 8.63,10.07 v4(9.02,10.07)
  L4_INT_2 w0.102: P1.13 1.08,3.83 2.79,5.54 4.98,5.54 6.96,7.52 6.96,7.58 7.67,8.29
SPIM_NSS: length 12.7
  L4_INT_2 w0.076: 8.89,8.29 8.89,9.21 v4(8.53,9.57)
  L4_INT_2 w0.102: P1.15 2.56,1.16 5.03,3.63 5.69,3.63 7.87,5.82 7.87,6.76 8.89,7.77 8.89,8.29
SPIM_SCLK: length 13.5
  L3_INT_1 w0.076: 8.28,8.29 8.28,8.69 8.25,8.71 8.25,9.68 8.53,9.95 v3(8.53,10.07)
  L3_INT_1 w0.102: v4(7.29,6.45) 7.29,6.55 8.05,7.32 8.05,7.72 8.28,7.95 8.28,8.29
  L4_INT_2 w0.102: P1.14 1.16,2.56 2.57,3.96 5.59,3.96 7.29,5.66 v4(7.29,6.45)
SWDCLK: length 10
  TOP w0.117: U1.C8 10.52,8.32 11.3,7.54 11.3,4.7 13.99,2.01 P1.24
SWDIO: length 10.3
  TOP w0.117: P1.25 15.26,1.38 11.71,4.93 11.71,7.67 11.02,8.36 U1.B8
TCVCM: length 5.5
  L3_INT_1 w0.076: v3(8.53,11.57) 8.53,12.76 8.41,12.88 8.41,13.11
  L3_INT_1 w0.203: 8.41,13.11 8.41,14.34 v5(6.48,16.26)
TEST: length 6.7
  TOP w0.076: 12.02,9.7 11.81,9.7 11.69,9.82 10.93,9.82 10.92,9.82 10.78,9.97 10.77,9.98 10.77,11.32 U1.C2
  TOP w0.117: 12.02,9.7 12.7,9.02 12.7,8.75 13.58,7.87 R6.2 v5(14.73,7.87)
TX1: length 2.6
  TOP w0.279: U1.H1 arc(7.73,12.14) 7.49,12.32
  TOP w0.516: 7.49,12.32 arc(6.69,12.89) L3.1
TX2: length 2.7
  TOP w0.279: U1.H3 arc(7.72,11) 7.49,10.79
  TOP w0.516: 7.49,10.79 arc(6.72,10.13) L1.1
TXVCASC: length 6.1
  TOP w0.381: C28.1 v5(7.34,16.16)
  L3_INT_1 w0.203: v3(9.02,11.57) 8.89,11.71 8.89,14.61 v5(7.34,16.16)
USB_VBUS: length 12.8
  TOP w0.254: U1.D1 v4(10.02,12.55)
  L4_INT_2 w0.508: P1.47 13.99,20.68 15.19,19.48 15.19,16.56 11.18,12.55 v4(10.02,12.55)
VEN: length 9.4
  TOP w0.203: R9.2 v5(17.78,7.87)
  L4_INT_2 w0.203: v4(11.02,11.07) 13.74,11.07 15.62,9.19 15.62,8.64 16.38,7.87 v5(17.78,7.87)
VMID: length 3.9
  TOP w0.117: C5.1 6.94,6.72 6.81,6.86 6.81,7.44 7.41,8.05 7.41,8.2 7.43,8.22 7.43,8.9 8.02,9.5 U1.H6
VREF: length 10.4
  L3_INT_1 w0.254: v3(10.02,11.57) 10.02,11.59 10.36,11.93
  L3_INT_1 w0.381: v5(11.05,14.38) 11.05,12.61 10.36,11.93
  L4_INT_2 w0.203: v5(11.05,14.38) 10.54,14.89 10.54,15.37 10.74,15.57 11.89,15.57 12.4,16.08 12.4,19.1 v5(11.81,19.68)
VTUNE1: length 10.5
  TOP w0.117: v1(7.47,7.44) 7.8,7.78 7.8,8.31 7.68,8.43 7.68,8.73 U1.H7
  L3_INT_1 w0.102: v1(7.47,7.44) 6.86,7.44 5,5.59 1.65,5.59 0.87,6.37 P1.11
VTUNE2: length 15.3
  L3_INT_1 w0.076: v3(8.02,8.57) 8.02,9.68 8.28,9.93 8.28,12.7 8,12.98 8,13.11
  L3_INT_1 w0.102: P1.3 1.03,16.53 1.4,16.89 5.59,16.89 5.84,16.64 5.84,16.31 8,14.15 8,13.11
VUP: length 18.5
  TOP w0.254: U1.F1 9.02,13.22 9.02,13.22
  TOP w0.381: C29.1 8.77,18.37 ; C29.1 8.77,17.38 ; C29.1 9.19,17.88
  TOP w0.889: v1(8.85,19.01) 8.91,19.07 P1.51 8.87,21.53 9.83,19.08
  L4_INT_2 w0.889: v1(9.63,16.64) 9.19,17.08 v1(9.19,17.22) 8.85,17.57 v1(8.85,19.01) 8.91,19.07 P1.51
  BOTTOM w0.889: P1.51 8.91,19.07 v1(8.85,19.01) 8.85,17.57 v1(9.19,17.22) 9.63,16.78 v1(9.63,16.64)
XTAL1: length 4.7
  TOP w0.117: R1.2 10.34,6.32 10.01,6.65 Y1.1 9.52,7.63 9.02,8.14 9.02,8.57 U1.F8
XTAL2: length 5.3
  TOP w0.117: U1.G8 8.53,8.31 8.34,8.12 8.34,7.68 7.89,7.23 7.89,6.27 8.32,5.84 Y1.3 8.46,5.41 8.24,5.18 7.56,5.18 7.37,4.99 C2.1

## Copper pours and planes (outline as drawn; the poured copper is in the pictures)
GND on TOP: 21.08,0.51 0.51,0.51 0.51,20.87 0.72,21.08 21.08,21.08 ; 3 cut-outs
GND on BOTTOM, L2_GND_1, L5_GND_2: 21.08,0.51 0.51,0.51 0.51,20.87 0.72,21.08 21.08,21.08
GND on L4_INT_2: 21.08,0.51 0.51,0.51 0.51,20.87 0.72,21.08 21.08,21.08 ; 9 cut-outs
VBATPWR on TOP: 12.25,11.27 12.64,11.27 12.85,11.47 15.86,11.47 15.98,11.35 16.49,11.35 16.68,11.16 16.68,9.78 16.51,9.61 15.56,9.61 15.47,9.7 15.47,10.01 15.41,10.07 12.61,10.07 12.12,10.56 12.12,11.14
VDDBOOST on TOP: 12.16,14.04 10.85,12.73 10.85,12.51 10.93,12.43 11.27,12.43 11.82,12.98 12.09,12.98 13.44,14.33 13.44,18.82 13.21,19.05 11.7,19.05 11,18.35 11,17.59 11.18,17.41 12.06,17.41 12.16,17.31
BOOST_LX on TOP: 15.5,11.97 15.5,13.4 13.06,13.4 13,13.34 13,12.79 12.78,12.57 11.99,12.57 11.85,12.44 11.85,12.03 11.91,11.97
VUP on TOP: 10.39,18.54 10.39,17.63 9.86,17.09 9.86,16.46 9.52,16.13 9.52,13.21 9.02,12.7 8.51,13.21 8.51,19.13 8.81,19.43 10.29,19.43 10.4,19.32 10.4,18.55

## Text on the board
BOTTOM: 9 OF 11 | L6_SS
Board Geometry/Soldermask Bottom: 10 OF 11 | SECONDARY SOLDERMASK
Ref Des/Silkscreen Bottom: 170-54814-A | PNEV7642MA | 11 OF 11 | SECONDARY SILKSCREEN
User.Comments: 1 OF 1 | TEST PROBE | 1/1 | 2
TOP: 4 OF 11 | L1_PS
Board Geometry/Soldermask Top: 3 OF 11 | PRIMARY SOLDERMASK
Ref Des/Silkscreen Top: 2 OF 11 | PRIMARY SILKSCREEN | A
L2_GND_1: 5 0F 11 | L2_GND_1
L3_INT_1: 6 OF 11 | L3_INT_1
L4_INT_2: 7 OF 11 | L4_INT_2
L5_GND_2: 8 OF 11 | L5_GND_2
XSECTION_CHART: SCALE: NONE | *  SURFACE - AIR 0 MIL | *  DIELECTRIC - DRY_FILM_MASK 0.42 MIL | L1 TOP CONDUCTOR - 1/2OZ_COPPER_PLATED 0.35 MIL | *  DIELECTRIC - FR-4 2.95 MIL | L2 L2_GND_1 PLANE - 1/2OZ_COPPER 0.6 MIL | *  DIELECTRIC - FR-4 4 MIL | L3 L3_INT_1 CONDUCTOR - 1/2OZ_COPPER 0.6 MIL | *  DIELECTRIC - FR-4 13.58 MIL | L4 L4_INT_2 CONDUCTOR - 1/2OZ_COPPER 0.6 MIL | L5 L5_GND_2 PLANE - 1/2OZ_COPPER 0.6 MIL | L6 BOTTOM CONDUCTOR - 1/2OZ_COPPER_PLATED 0.35 MIL | DESIGN CROSS SECTION CHART | ___________________________ | TOTAL THICKNESS 31.42 MIL | 1-6 | 1-2 | 2-3 | 3-4 | 23. PLATED HALF HOLES(CASTELLATION HOLES) 56 POS. | TYPE: LPI OR EQUIVALENT. | A. LOCATION = +/-.002" OF PLATED PADS. | B. DIAMETER OR SIZE = +/-.002 OF ORIGINAL DATA | DIMENSIONS ARE IN mm | CASTELLATION HOLES | 22 | 21 | 23 | 8 | 18 | 56x PLACES | 1 | DETAIL | LAYER STACKUP | A
DIMENSION: 0.8(+0.1/-0.1) mm THICK | PRIMARY DATUM | GRID ORIGIN
BODY_CENTER: 1 OF 11 | PASTEMASK TOP
PASTEMASK_BOTTOM: 12 OF 12 | SECONDARY PASTEMASK
User.9: PIN14 | PIN1 | SPIM_MOSI | SPIM_SCLK | MOD_RXN | GND | MOD_TX2 | MOD_RXP | MOD_TX1 | VTUNE1 | VTUNE2 | AD1 | I2CM_SDA | PRD1 | I2CM_SCL | PRD2 | ATX_A | ATX_C | GPIO4 | GPIO1 | ATX_B | ATX_D | GPIO3 | GPIO2 | GPIO5 | CT_CLK | SPIM_NSS | CT_IO | SPIM_MISO | CT_INT | AUX1 | AUX2 | VDDPA | HOSTIF_SEL0 | VUP | HOSTIF_SEL1 | CLK_IN | VBAT | USB_VBUS | SWDCLK | VBATPWR | SWDIO | IRQ | VDDIO | DWL_REQ | VEN-R10- | GPIO0
User.14: 22. THIS FAB_VIAFILL.ART SHOWS LOCATIONS OF VIA-IN-PAD TO BE FILLED." | 2 | FAB SUPPLIER: DISREGARD THIS PAGE IF VIA-IN-PAD DOESN'T APPLY OR NOT REQUIRED ON FAB.ART
User.15: ALL PARTS, MATERIALS AND FINISHED | ASSEMBLY SHALL NOT CONTAIN ANY OF | THE SUBSTANCES OF VERY HIGH CONCERN | (SVHC) ABOVE THE THRESHOLD VALUE PER | THE CURRENT ECHA LIST OF SVHC'S AND | WITH ANNEX XIV AND ANNEX XVII OF REACH | DIRECTIVE 76/769/EEC. A CERTIFICATE OF | COMPLIANCE IS REQUIRED UPON REQUEST. | ASSEMBLY SHALL MEET THE RoHS | COMMISSION DELEGATED DIRECTIVE (EU) | 2015/863 OF 31 MARCH  2015 AMENDING | ANNEX II TO DIRECTIVE 2011/65/EU. A | CERTIFICATE OF COMPLIANCE IS | REQUIRED UPON REQUEST.
User.18: TRACE WIDTH | (MILS) | IMPEDANCE | (OHMS) | TRACE SPACING | ---- | -- | 4.20 | 90 | 8.00 | DIFFERENTIAL PAIR
User.20: FIGURE | FINISHED_SIZE | 5.1 | DRILL CHART: TOP to L2_GND_1 | ALL UNITS ARE IN MILS | TOLERANCE_DRILL | +0.0/-5.1 | PLATED | QTY | 43
User.21: FIGURE | FINISHED_SIZE | 8.0 | 8.1 | 20.0 | 25.0 | DRILL CHART: TOP to BOTTOM | ALL UNITS ARE IN MILS | TOLERANCE_DRILL | +0.0/-8.0 | +0.0/-8.1 | +2.0/-2.0 | PLATED | NON-PLATED | QTY | 141 | 31 | 56 | 1
User.22: FIGURE | FINISHED_SIZE | 5.1 | DRILL CHART: L2_GND_1 to L3_INT_1 | ALL UNITS ARE IN MILS | TOLERANCE_DRILL | +0.0/-5.1 | PLATED | QTY | 34
User.24: FIGURE | FINISHED_SIZE | 5.1 | DRILL CHART: L3_INT_1 to L4_INT_2 | ALL UNITS ARE IN MILS | TOLERANCE_DRILL | +0.0/-5.1 | PLATED | QTY | 17
